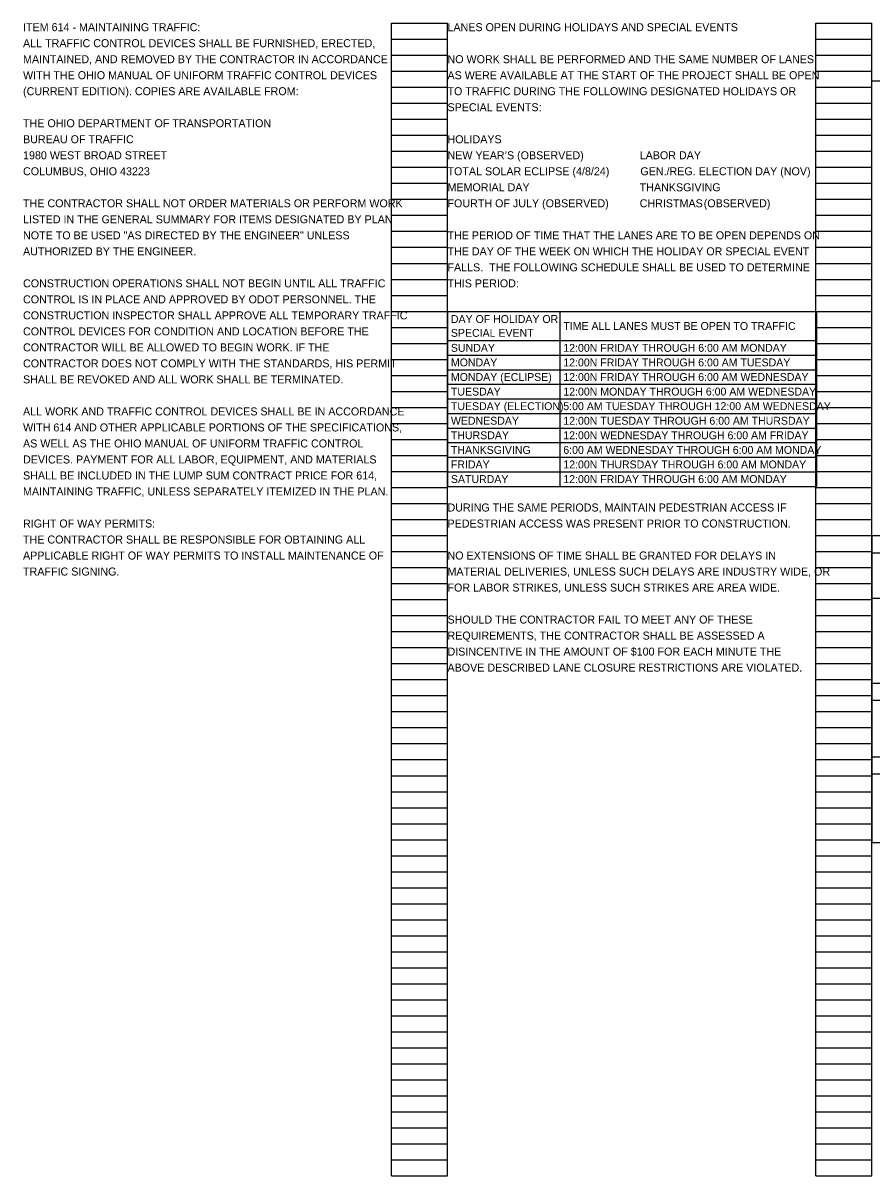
# Model space of a CAD drawing. Extents: x -23 to 32, y -58.1 to 21.1.
# Drawn here: x 2.4 to 17.24, y 0.98 to 21.14 of the extents above; entities that cross this region are included whole.
import ezdxf

# ---------------------------------------------------------------- set-up
doc = ezdxf.new("R2010")
doc.units = 0
for name, color, linetype in [('Default', 7, 'Continuous'), ('SH_Data', 7, 'Continuous'), ('SH_Text', 7, 'Continuous')]:
    doc.layers.add(name, color=color, linetype=linetype)

msp = doc.modelspace()

# ---------------------------------------------------------------- linework, layer by layer
at = {"layer": 'Default'}
for p, q in [((9.82, 16.1), (16.27, 16.1)), ((9.82, 16.1), (9.82, 13.04)), ((11.785, 16.1), (11.785, 13.04)), ((16.27, 16.1), (16.27, 13.04)), ((9.82, 15.59), (16.27, 15.59)), ((9.82, 15.335), (16.27, 15.335)), ((9.82, 15.08), (16.27, 15.08)), ((9.82, 14.825), (16.27, 14.825)), ((9.82, 14.57), (16.27, 14.57)), ((9.82, 14.315), (16.27, 14.315)), ((9.82, 14.06), (16.27, 14.06)), ((9.82, 13.805), (16.27, 13.805)), ((9.82, 13.55), (16.27, 13.55)), ((9.82, 13.295), (16.27, 13.295)), ((9.82, 13.04), (16.27, 13.04)), ((17.24, 12.18), (22.895, 12.18)), ((17.24, 12.18), (17.24, 6.81)), ((17.24, 11.88), (22.895, 11.88)), ((17.24, 11.085), (22.895, 11.085)), ((17.24, 9.6), (22.895, 9.6)), ((17.24, 9.3), (22.895, 9.3)), ((17.24, 8.31), (22.895, 8.31)), ((17.24, 8.01), (22.895, 8.01)), ((17.24, 6.81), (22.895, 6.81))]:
    msp.add_line(p, q, dxfattribs=at)
at = {"layer": 'SH_Data'}
for p, q in [((8.84, 0.98), (8.84, 21.14)), ((8.84, 21.14), (9.82, 21.14)), ((9.82, 0.98), (9.82, 21.14)), ((16.26, 0.98), (16.26, 21.14)), ((16.26, 21.14), (17.24, 21.14)), ((17.24, 0.98), (17.24, 21.14)), ((8.84, 20.86), (9.82, 20.86)), ((16.26, 20.86), (17.24, 20.86)), ((8.84, 20.58), (9.82, 20.58)), ((16.26, 20.58), (17.24, 20.58)), ((8.84, 20.3), (9.82, 20.3)), ((16.26, 20.3), (17.24, 20.3)), ((8.84, 20.02), (9.82, 20.02)), ((16.26, 20.02), (17.24, 20.02)), ((8.84, 19.74), (9.82, 19.74)), ((16.26, 19.74), (17.24, 19.74)), ((8.84, 19.46), (9.82, 19.46)), ((16.26, 19.46), (17.24, 19.46)), ((8.84, 19.18), (9.82, 19.18)), ((16.26, 19.18), (17.24, 19.18)), ((8.84, 18.9), (9.82, 18.9)), ((16.26, 18.9), (17.24, 18.9)), ((8.84, 18.62), (9.82, 18.62)), ((16.26, 18.62), (17.24, 18.62)), ((8.84, 18.34), (9.82, 18.34)), ((16.26, 18.34), (17.24, 18.34)), ((8.84, 18.06), (9.82, 18.06)), ((16.26, 18.06), (17.24, 18.06)), ((8.84, 17.78), (9.82, 17.78)), ((16.26, 17.78), (17.24, 17.78)), ((8.84, 17.5), (9.82, 17.5)), ((16.26, 17.5), (17.24, 17.5)), ((8.84, 17.22), (9.82, 17.22)), ((16.26, 17.22), (17.24, 17.22)), ((8.84, 16.94), (9.82, 16.94)), ((16.26, 16.94), (17.24, 16.94)), ((8.84, 16.66), (9.82, 16.66)), ((16.26, 16.66), (17.24, 16.66)), ((8.84, 16.38), (9.82, 16.38)), ((16.26, 16.38), (17.24, 16.38)), ((8.84, 16.1), (9.82, 16.1)), ((16.26, 16.1), (17.24, 16.1)), ((8.84, 15.82), (9.82, 15.82)), ((16.26, 15.82), (17.24, 15.82)), ((8.84, 15.54), (9.82, 15.54)), ((16.26, 15.54), (17.24, 15.54)), ((8.84, 15.26), (9.82, 15.26)), ((16.26, 15.26), (17.24, 15.26)), ((8.84, 14.98), (9.82, 14.98)), ((16.26, 14.98), (17.24, 14.98)), ((8.84, 14.7), (9.82, 14.7)), ((16.26, 14.7), (17.24, 14.7)), ((8.84, 14.42), (9.82, 14.42)), ((16.26, 14.42), (17.24, 14.42)), ((8.84, 14.14), (9.82, 14.14)), ((16.26, 14.14), (17.24, 14.14)), ((8.84, 13.86), (9.82, 13.86)), ((16.26, 13.86), (17.24, 13.86)), ((8.84, 13.58), (9.82, 13.58)), ((16.26, 13.58), (17.24, 13.58)), ((8.84, 13.3), (9.82, 13.3)), ((16.26, 13.3), (17.24, 13.3)), ((8.84, 13.02), (9.82, 13.02)), ((16.26, 13.02), (17.24, 13.02)), ((8.84, 12.74), (9.82, 12.74)), ((16.26, 12.74), (17.24, 12.74)), ((8.84, 12.46), (9.82, 12.46)), ((16.26, 12.46), (17.24, 12.46)), ((8.84, 12.18), (9.82, 12.18)), ((16.26, 12.18), (17.24, 12.18)), ((8.84, 11.9), (9.82, 11.9)), ((16.26, 11.9), (17.24, 11.9)), ((8.84, 11.62), (9.82, 11.62)), ((16.26, 11.62), (17.24, 11.62)), ((8.84, 11.34), (9.82, 11.34)), ((16.26, 11.34), (17.24, 11.34)), ((8.84, 11.06), (9.82, 11.06)), ((16.26, 11.06), (17.24, 11.06)), ((8.84, 10.78), (9.82, 10.78)), ((16.26, 10.78), (17.24, 10.78)), ((8.84, 10.5), (9.82, 10.5)), ((16.26, 10.5), (17.24, 10.5)), ((8.84, 10.22), (9.82, 10.22)), ((16.26, 10.22), (17.24, 10.22)), ((8.84, 9.94), (9.82, 9.94)), ((16.26, 9.94), (17.24, 9.94)), ((8.84, 9.66), (9.82, 9.66)), ((16.26, 9.66), (17.24, 9.66)), ((8.84, 9.38), (9.82, 9.38)), ((16.26, 9.38), (17.24, 9.38)), ((8.84, 9.1), (9.82, 9.1)), ((16.26, 9.1), (17.24, 9.1)), ((8.84, 8.82), (9.82, 8.82)), ((16.26, 8.82), (17.24, 8.82)), ((8.84, 8.54), (9.82, 8.54)), ((16.26, 8.54), (17.24, 8.54)), ((8.84, 8.26), (9.82, 8.26)), ((16.26, 8.26), (17.24, 8.26)), ((8.84, 7.98), (9.82, 7.98)), ((16.26, 7.98), (17.24, 7.98)), ((8.84, 7.7), (9.82, 7.7)), ((16.26, 7.7), (17.24, 7.7)), ((8.84, 7.42), (9.82, 7.42)), ((16.26, 7.42), (17.24, 7.42)), ((8.84, 7.14), (9.82, 7.14)), ((16.26, 7.14), (17.24, 7.14)), ((8.84, 6.86), (9.82, 6.86)), ((16.26, 6.86), (17.24, 6.86)), ((8.84, 6.58), (9.82, 6.58)), ((16.26, 6.58), (17.24, 6.58)), ((8.84, 6.3), (9.82, 6.3)), ((16.26, 6.3), (17.24, 6.3)), ((8.84, 6.02), (9.82, 6.02)), ((16.26, 6.02), (17.24, 6.02)), ((8.84, 5.74), (9.82, 5.74)), ((16.26, 5.74), (17.24, 5.74)), ((8.84, 5.46), (9.82, 5.46)), ((16.26, 5.46), (17.24, 5.46)), ((8.84, 5.18), (9.82, 5.18)), ((16.26, 5.18), (17.24, 5.18)), ((8.84, 4.9), (9.82, 4.9)), ((16.26, 4.9), (17.24, 4.9)), ((8.84, 4.62), (9.82, 4.62)), ((16.26, 4.62), (17.24, 4.62)), ((8.84, 4.34), (9.82, 4.34)), ((16.26, 4.34), (17.24, 4.34)), ((8.84, 4.06), (9.82, 4.06)), ((16.26, 4.06), (17.24, 4.06)), ((8.84, 3.78), (9.82, 3.78)), ((16.26, 3.78), (17.24, 3.78)), ((8.84, 3.5), (9.82, 3.5)), ((16.26, 3.5), (17.24, 3.5)), ((8.84, 3.22), (9.82, 3.22)), ((16.26, 3.22), (17.24, 3.22)), ((8.84, 2.94), (9.82, 2.94)), ((16.26, 2.94), (17.24, 2.94)), ((8.84, 2.66), (9.82, 2.66)), ((16.26, 2.66), (17.24, 2.66)), ((8.84, 2.38), (9.82, 2.38)), ((16.26, 2.38), (17.24, 2.38)), ((8.84, 2.1), (9.82, 2.1)), ((16.26, 2.1), (17.24, 2.1)), ((8.84, 1.82), (9.82, 1.82)), ((16.26, 1.82), (17.24, 1.82)), ((8.84, 1.54), (9.82, 1.54)), ((16.26, 1.54), (17.24, 1.54)), ((8.84, 1.26), (9.82, 1.26)), ((16.26, 1.26), (17.24, 1.26)), ((8.84, 0.98), (9.82, 0.98)), ((16.26, 0.98), (17.24, 0.98))]:
    msp.add_line(p, q, dxfattribs=at)
at = {"layer": 'SH_Text'}
msp.add_line((17.233, 20.131), (19.165, 20.131), dxfattribs=at)

# ---------------------------------------------------------------- texts
at = {"layer": 'Default'}
for s, p in [('DAY OF HOLIDAY OR ', (9.88, 15.897)), ('SPECIAL EVENT', (9.88, 15.655)), ('TIME ALL LANES MUST BE OPEN TO TRAFFIC', (11.845, 15.776)), ('SUNDAY', (9.88, 15.393)), ('12:00N FRIDAY THROUGH 6:00 AM MONDAY', (11.845, 15.393)), ('MONDAY', (9.88, 15.138)), ('12:00N FRIDAY THROUGH 6:00 AM TUESDAY', (11.845, 15.138)), ('MONDAY (ECLIPSE)', (9.88, 14.883)), ('12:00N FRIDAY THROUGH 6:00 AM WEDNESDAY', (11.845, 14.883)), ('TUESDAY', (9.88, 14.628)), ('12:00N MONDAY THROUGH 6:00 AM WEDNESDAY', (11.845, 14.628)), ('TUESDAY (ELECTION)', (9.88, 14.373)), ('5:00 AM TUESDAY THROUGH 12:00 AM WEDNESDAY', (11.845, 14.373)), ('WEDNESDAY', (9.88, 14.118)), ('12:00N TUESDAY THROUGH 6:00 AM THURSDAY', (11.845, 14.118)), ('THURSDAY', (9.88, 13.864)), ('12:00N WEDNESDAY THROUGH 6:00 AM FRIDAY', (11.845, 13.864)), ('THANKSGIVING', (9.88, 13.608)), ('6:00 AM WEDNESDAY THROUGH 6:00 AM MONDAY', (11.845, 13.608)), ('FRIDAY', (9.88, 13.354)), ('12:00N THURSDAY THROUGH 6:00 AM MONDAY', (11.845, 13.354)), ('SATURDAY', (9.88, 13.098)), ('12:00N FRIDAY THROUGH 6:00 AM MONDAY', (11.845, 13.098))]:
    msp.add_text(s, height=0.138, dxfattribs=at).set_placement(p)
at = {"layer": 'SH_Data'}
for s, p in [('LANES OPEN DURING HOLIDAYS AND SPECIAL EVENTS', (9.82, 21)), ('NO WORK SHALL BE PERFORMED AND THE SAME NUMBER OF LANES ', (9.82, 20.44)), ('AS WERE AVAILABLE AT THE START OF THE PROJECT SHALL BE OPEN ', (9.82, 20.16)), ('TO TRAFFIC DURING THE FOLLOWING DESIGNATED HOLIDAYS OR ', (9.82, 19.88)), ('SPECIAL EVENTS:', (9.82, 19.6)), ('HOLIDAYS', (9.82, 19.04)), ('NEW YEAR’S (OBSERVED)', (9.82, 18.76)), ('LABOR DAY', (13.18, 18.76)), ('TOTAL SOLAR ECLIPSE (4/8/24)', (9.82, 18.48)), ('           GEN./REG. ELECTION DAY (NOV)', (12.62, 18.48)), ('MEMORIAL DAY ', (9.82, 18.2)), ('THANKSGIVING', (13.18, 18.2)), ('FOURTH OF JULY\xa0(OBSERVED)', (9.82, 17.92)), ('CHRISTMAS', (13.18, 17.92)), ('(OBSERVED)', (14.3, 17.92)), ('THE PERIOD OF TIME THAT THE LANES ARE TO BE OPEN DEPENDS ON ', (9.82, 17.36)), ('THE DAY OF THE WEEK ON WHICH THE HOLIDAY OR SPECIAL EVENT ', (9.82, 17.08)), ('FALLS.  THE FOLLOWING SCHEDULE SHALL BE USED TO DETERMINE ', (9.82, 16.8)), ('THIS PERIOD:', (9.82, 16.52)), ('DURING THE SAME PERIODS, MAINTAIN PEDESTRIAN ACCESS IF ', (9.82, 12.6)), ('PEDESTRIAN ACCESS WAS PRESENT PRIOR TO CONSTRUCTION. ', (9.82, 12.32)), ('NO EXTENSIONS OF TIME SHALL BE GRANTED FOR DELAYS IN ', (9.82, 11.76)), ('MATERIAL DELIVERIES, UNLESS SUCH DELAYS ARE INDUSTRY WIDE, OR ', (9.82, 11.48)), ('FOR LABOR STRIKES, UNLESS SUCH STRIKES ARE AREA WIDE.', (9.82, 11.2)), ('SHOULD THE CONTRACTOR FAIL TO MEET ANY OF THESE ', (9.82, 10.64)), ('REQUIREMENTS, THE CONTRACTOR SHALL BE ASSESSED A ', (9.82, 10.36)), ('DISINCENTIVE IN THE AMOUNT OF $100 FOR EACH MINUTE THE ', (9.82, 10.08)), ('ABOVE DESCRIBED LANE CLOSURE RESTRICTIONS ARE VIOLATED.', (9.82, 9.8))]:
    msp.add_text(s, height=0.14, dxfattribs=at).set_placement(p)
at = {"layer": 'SH_Text'}
for s, p in [('ITEM 614 - MAINTAINING TRAFFIC:', (2.4, 21)), ('ALL TRAFFIC CONTROL DEVICES SHALL BE FURNISHED, ERECTED, ', (2.4, 20.72)), ('MAINTAINED, AND REMOVED BY THE CONTRACTOR IN ACCORDANCE ', (2.4, 20.44)), ('WITH THE OHIO MANUAL OF UNIFORM TRAFFIC CONTROL DEVICES ', (2.4, 20.16)), ('(CURRENT EDITION). COPIES ARE AVAILABLE FROM:', (2.4, 19.88)), ('THE OHIO DEPARTMENT OF TRANSPORTATION', (2.4, 19.32)), ('BUREAU OF TRAFFIC', (2.4, 19.04)), ('1980 WEST BROAD STREET', (2.4, 18.76)), ('COLUMBUS, OHIO 43223', (2.4, 18.48)), ('THE CONTRACTOR SHALL NOT ORDER MATERIALS OR PERFORM WORK ', (2.4, 17.92)), ('LISTED IN THE GENERAL SUMMARY FOR ITEMS DESIGNATED BY PLAN ', (2.4, 17.64)), ('NOTE TO BE USED "AS DIRECTED BY THE ENGINEER" UNLESS ', (2.4, 17.36)), ('AUTHORIZED BY THE ENGINEER.', (2.4, 17.08)), ('CONSTRUCTION OPERATIONS SHALL NOT BEGIN UNTIL ALL TRAFFIC ', (2.4, 16.52)), ('CONTROL IS IN PLACE AND APPROVED BY ODOT PERSONNEL. THE ', (2.4, 16.24)), ('CONSTRUCTION INSPECTOR SHALL APPROVE ALL TEMPORARY TRAFFIC ', (2.4, 15.96)), ('CONTROL DEVICES FOR CONDITION AND LOCATION BEFORE THE ', (2.4, 15.68)), ('CONTRACTOR WILL BE ALLOWED TO BEGIN WORK. IF THE ', (2.4, 15.4)), ('CONTRACTOR DOES NOT COMPLY WITH THE STANDARDS, HIS PERMIT ', (2.4, 15.12)), ('SHALL BE REVOKED AND ALL WORK SHALL BE TERMINATED.', (2.4, 14.84)), ('ALL WORK AND TRAFFIC CONTROL DEVICES SHALL BE IN ACCORDANCE ', (2.4, 14.28)), ('WITH 614 AND OTHER APPLICABLE PORTIONS OF THE SPECIFICATIONS, ', (2.4, 14)), ('AS WELL AS THE OHIO MANUAL OF UNIFORM TRAFFIC CONTROL ', (2.4, 13.72)), ('DEVICES. PAYMENT FOR ALL LABOR, EQUIPMENT, AND MATERIALS ', (2.4, 13.44)), ('SHALL BE INCLUDED IN THE LUMP SUM CONTRACT PRICE FOR 614, ', (2.4, 13.16)), ('MAINTAINING TRAFFIC, UNLESS SEPARATELY ITEMIZED IN THE PLAN.', (2.4, 12.88)), ('RIGHT OF WAY PERMITS:', (2.4, 12.32)), ('THE CONTRACTOR SHALL BE RESPONSIBLE FOR OBTAINING ALL ', (2.4, 12.04)), ('APPLICABLE RIGHT OF WAY PERMITS TO INSTALL MAINTENANCE OF ', (2.4, 11.76)), ('TRAFFIC SIGNING.', (2.4, 11.48))]:
    msp.add_text(s, height=0.14, dxfattribs=at).set_placement(p)

doc.saveas('drawing.dxf')
